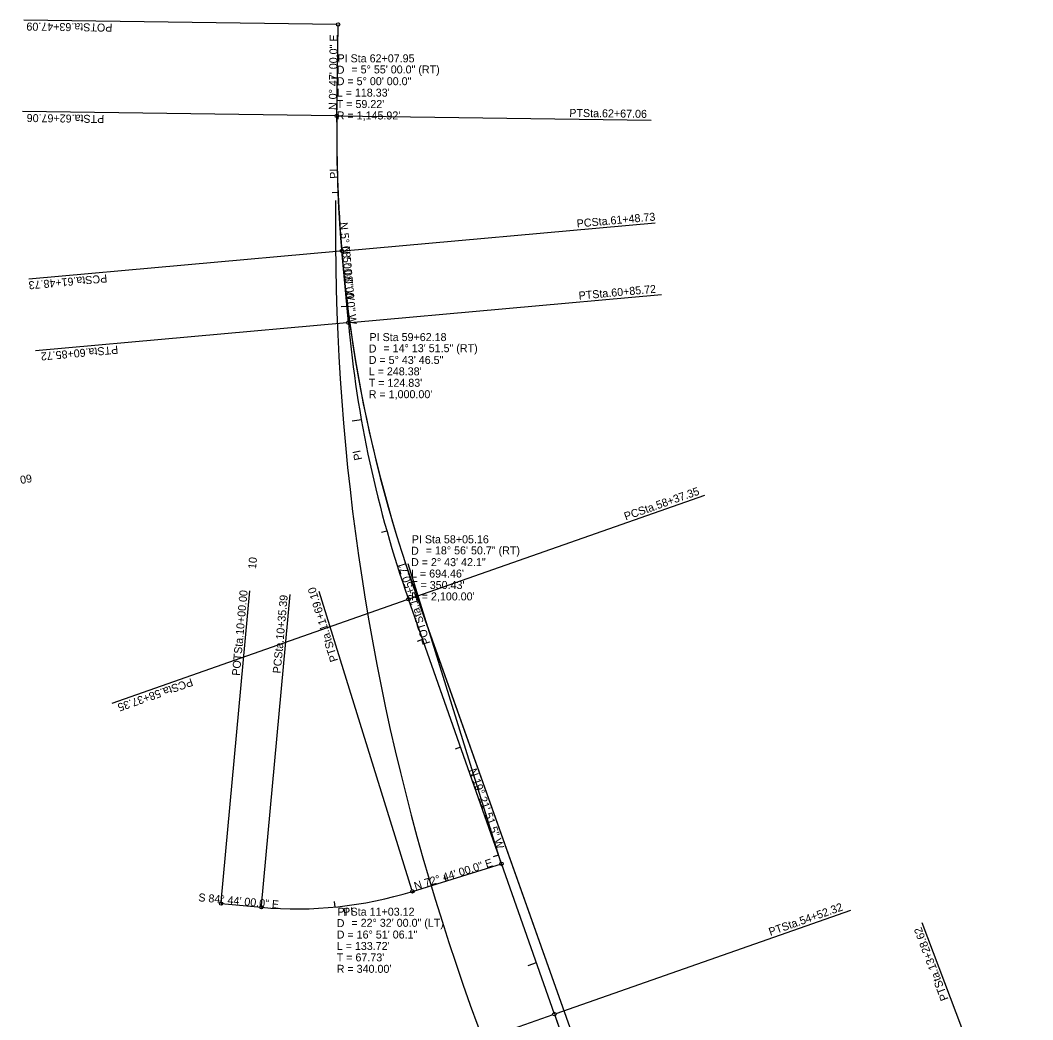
# Model space of a CAD drawing. Extents: x 1615740 to 1617154, y 899624 to 904812.
# Drawn here: x 1615740 to 1616626, y 903937 to 904812 of the extents above; entities that cross this region are included whole.
import ezdxf

# ---------------------------------------------------------------- set-up
doc = ezdxf.new("R2010")
doc.units = 0
for name, color, linetype in [('Default', 7, 'Continuous'), ('Exist Plan Preparation Drainage Flow Arrows', 7, 'Continuous'), ('Exist Plan Preparation Drainage Notes Label', 7, 'Continuous'), ('Exist Structure Minor Pipes CMP 15 Inch Text', 7, 'Continuous'), ('Exist Structure Minor Pipes CMP 24 Inch Text', 7, 'Continuous'), ('Exist Structure Minor Pipes RCP 12 Inch Text', 7, 'Continuous'), ('Exist Structure Minor Pipes RCP 24 Inch Text', 7, 'Continuous'), ('Prop Plan Preparation Sag', 7, 'Continuous'), ('Scratch_Level_7', 7, 'Continuous')]:
    doc.layers.add(name, color=color, linetype=linetype)

msp = doc.modelspace()

# ---------------------------------------------------------------- linework, layer by layer
at = {"layer": 'Default'}
for p, q in [((1616561.34, 902975.04), (1616086.7, 904309.23)), ((1616561.34, 902975.04), (1616086.7, 904309.23)), ((1616342.41, 903590.45), (1616086.73, 904309.16)), ((1616207.75, 903941.79), (1616102.54, 904241.15))]:
    msp.add_line(p, q, dxfattribs=at)
for centre, radius, start, end in [((1617217.29, 904711.44), 1200, 179.21667, 199.58304), ((1617217.29, 904711.44), 1200, 179.21667, 199.58304), ((1618016.2, 904626.61), 2000, 179.21665, 214.80209), ((1618849.35, 904870.2), 2800, 199.3643, 204.77008)]:
    msp.add_arc(centre, radius, start, end, dxfattribs=at)
at = {"layer": 'Exist Plan Preparation Drainage Flow Arrows'}
for p, q in [((1616038.85, 904462.19), (1616030.97, 904460.79)), ((1616038.85, 904462.19), (1616030.97, 904460.79)), ((1616038.85, 904462.19), (1616030.97, 904460.79)), ((1616038.85, 904462.19), (1616030.97, 904460.79)), ((1615916.17, 904038.64), (1615916.9, 904046.61)), ((1615916.17, 904038.64), (1615916.9, 904046.61)), ((1615916.17, 904038.64), (1615916.9, 904046.61)), ((1615916.17, 904038.64), (1615916.9, 904046.61)), ((1616191.94, 903986.77), (1616184.4, 903984.12)), ((1616191.94, 903986.77), (1616184.4, 903984.12)), ((1616191.94, 903986.77), (1616184.4, 903984.12)), ((1616191.94, 903986.77), (1616184.4, 903984.12))]:
    msp.add_line(p, q, dxfattribs=at)
at = {"layer": 'Exist Plan Preparation Drainage Notes Label'}
for p, q in [((1616017.85, 904761.02), (1616012.85, 904761.08)), ((1616017.85, 904761.02), (1616012.85, 904761.08)), ((1616017.85, 904761.02), (1616012.85, 904761.08)), ((1616017.85, 904761.02), (1616012.85, 904761.08)), ((1616018.45, 904661.04), (1616013.45, 904660.81)), ((1616018.45, 904661.04), (1616013.45, 904660.81)), ((1616018.45, 904661.04), (1616013.45, 904660.81)), ((1616018.45, 904661.04), (1616013.45, 904660.81)), ((1616026.25, 904561.35), (1616021.27, 904560.9)), ((1616026.25, 904561.35), (1616021.27, 904560.9)), ((1616026.25, 904561.35), (1616021.27, 904560.9)), ((1616026.25, 904561.35), (1616021.27, 904560.9)), ((1616061.18, 904364.75), (1616056.37, 904363.39)), ((1616061.18, 904364.75), (1616056.37, 904363.39)), ((1616061.18, 904364.75), (1616056.37, 904363.39)), ((1616061.18, 904364.75), (1616056.37, 904363.39)), ((1616092.47, 904269.8), (1616087.75, 904268.14)), ((1616092.47, 904269.8), (1616087.75, 904268.14)), ((1616092.47, 904269.8), (1616087.75, 904268.14)), ((1616092.47, 904269.8), (1616087.75, 904268.14)), ((1616125.63, 904175.46), (1616120.91, 904173.8)), ((1616125.63, 904175.46), (1616120.91, 904173.8)), ((1616125.63, 904175.46), (1616120.91, 904173.8)), ((1616125.63, 904175.46), (1616120.91, 904173.8)), ((1616158.79, 904081.11), (1616154.07, 904079.46)), ((1616158.79, 904081.11), (1616154.07, 904079.46)), ((1616158.79, 904081.11), (1616154.07, 904079.46)), ((1616158.79, 904081.11), (1616154.07, 904079.46)), ((1616113.04, 904058.45), (1616111.55, 904063.23)), ((1616113.04, 904058.45), (1616111.55, 904063.23)), ((1616113.04, 904058.45), (1616111.55, 904063.23)), ((1616113.04, 904058.45), (1616111.55, 904063.23)), ((1616015.92, 904035.59), (1616015.43, 904040.57)), ((1616015.92, 904035.59), (1616015.43, 904040.57)), ((1616015.92, 904035.59), (1616015.43, 904040.57)), ((1616015.92, 904035.59), (1616015.43, 904040.57))]:
    msp.add_line(p, q, dxfattribs=at)
at = {"layer": 'Exist Structure Minor Pipes CMP 24 Inch Text'}
for p, q in [((1616017.33, 904722.71), (1616018.5, 904808.1)), ((1616017.4, 904728.08), (1616018.5, 904808.1)), ((1616027.53, 904547.13), (1616021.89, 904609.89)), ((1616207.75, 903941.79), (1616080.09, 904305.03)), ((1616083.53, 904049.28), (1616161.46, 904073.5)), ((1615916.17, 904038.64), (1615951.41, 904035.39))]:
    msp.add_line(p, q, dxfattribs=at)
for centre, radius, start, end in [((1617163.21, 904712.42), 1145.92, 179.21667, 185.13333), ((1617023.52, 904636.61), 1000, 185.13333, 199.3643), ((1615982.61, 904373.96), 340, 264.73333, 287.26667), ((1618849.35, 904870.2), 2800, 199.3643, 205.88101)]:
    msp.add_arc(centre, radius, start, end, dxfattribs=at)
at = {"layer": 'Exist Structure Minor Pipes RCP 12 Inch Text'}
msp.add_line((1616561.34, 902975.02), (1616086.69, 904309.48), dxfattribs=at)
msp.add_arc((1617217.31, 904711.62), 1200, 179.31667, 199.57988, dxfattribs=at)
at = {"layer": 'Prop Plan Preparation Sag'}
for p, q in [((1616017, 904808.12), (1615743.52, 904811.86)), ((1616017, 904808.12), (1615743.52, 904811.86)), ((1616017, 904808.12), (1615743.52, 904811.86)), ((1616017, 904808.12), (1615743.52, 904811.86)), ((1616015.9, 904728.1), (1615742.43, 904731.84)), ((1616018.9, 904728.06), (1616292.38, 904724.32)), ((1616018.9, 904728.06), (1616292.38, 904724.32)), ((1616018.9, 904728.06), (1616292.38, 904724.32)), ((1616023.39, 904610.02), (1616295.79, 904634.49)), ((1616023.39, 904610.02), (1616295.79, 904634.49)), ((1616023.39, 904610.02), (1616295.79, 904634.49)), ((1616020.4, 904609.75), (1615748, 904585.28)), ((1616029.02, 904547.27), (1616301.43, 904571.74)), ((1616029.02, 904547.27), (1616301.43, 904571.74)), ((1616029.02, 904547.27), (1616301.43, 904571.74)), ((1616026.04, 904547), (1615753.63, 904522.53)), ((1616081.5, 904305.53), (1616339.53, 904396.21)), ((1616081.5, 904305.53), (1616339.53, 904396.21)), ((1616081.5, 904305.53), (1616339.53, 904396.21)), ((1616161.02, 904074.93), (1616079.84, 904336.11)), ((1616161.02, 904074.93), (1616079.84, 904336.11)), ((1616161.02, 904074.93), (1616079.84, 904336.11)), ((1616161.02, 904074.93), (1616079.84, 904336.11)), ((1616078.67, 904304.53), (1615820.65, 904213.85)), ((1615916.3, 904040.13), (1615941.41, 904312.48)), ((1615916.3, 904040.13), (1615941.41, 904312.48)), ((1615916.3, 904040.13), (1615941.41, 904312.48)), ((1615916.3, 904040.13), (1615941.41, 904312.48)), ((1615951.54, 904036.89), (1615976.65, 904309.23)), ((1615951.54, 904036.89), (1615976.65, 904309.23)), ((1615951.54, 904036.89), (1615976.65, 904309.23)), ((1615951.54, 904036.89), (1615976.65, 904309.23)), ((1616083.09, 904050.71), (1616001.91, 904311.89)), ((1616083.09, 904050.71), (1616001.91, 904311.89)), ((1616083.09, 904050.71), (1616001.91, 904311.89)), ((1616083.09, 904050.71), (1616001.91, 904311.89)), ((1616209.17, 903942.29), (1616467.2, 904032.97)), ((1616209.17, 903942.29), (1616467.2, 904032.97)), ((1616209.17, 903942.29), (1616467.2, 904032.97)), ((1616626.29, 903765.86), (1616529.62, 904021.7)), ((1616206.34, 903941.29), (1615948.31, 903850.61))]:
    msp.add_line(p, q, dxfattribs=at)
for centre in [(1616018.5, 904808.1), (1616018.5, 904808.1), (1616018.5, 904808.1), (1616018.5, 904808.1), (1616017.4, 904728.08), (1616017.4, 904728.08), (1616017.4, 904728.08), (1616017.4, 904728.08), (1616021.89, 904609.89), (1616021.89, 904609.89), (1616021.89, 904609.89), (1616021.89, 904609.89), (1616027.53, 904547.13), (1616027.53, 904547.13), (1616027.53, 904547.13), (1616027.53, 904547.13), (1616080.09, 904305.03), (1616080.09, 904305.03), (1616080.09, 904305.03), (1616080.09, 904305.03), (1616161.46, 904073.5), (1616161.46, 904073.5), (1616161.46, 904073.5), (1616161.46, 904073.5), (1616083.53, 904049.28), (1616083.53, 904049.28), (1616083.53, 904049.28), (1616083.53, 904049.28), (1615916.17, 904038.64), (1615916.17, 904038.64), (1615916.17, 904038.64), (1615916.17, 904038.64), (1615951.41, 904035.39), (1615951.41, 904035.39), (1615951.41, 904035.39), (1615951.41, 904035.39), (1616207.75, 903941.79), (1616207.75, 903941.79), (1616207.75, 903941.79), (1616207.75, 903941.79)]:
    msp.add_circle(centre, 1.5, dxfattribs=at)

# ---------------------------------------------------------------- texts
at = {"layer": 'Default'}
for rotation, p in [(92.175, (1616018.43, 904673.26)), (92.175, (1616018.43, 904673.26)), (102.24882, (1616039.74, 904427.45)), (102.24882, (1616039.74, 904427.45)), (6, (1616023.36, 904027.64)), (6, (1616023.36, 904027.64))]:
    msp.add_text('PI ', height=7, rotation=rotation, dxfattribs=at).set_placement(p)
at = {"layer": 'Exist Structure Minor Pipes CMP 15 Inch Text'}
for s, rotation, p in [('N 0%%d 47\' 00.0" E', 89.21667, (1616017.27, 904733.22)), ('N 0%%d 47\' 00.0" E', 89.21667, (1616017.27, 904733.22)), ('N 0%%d 47\' 00.0" E', 89.21667, (1616017.27, 904733.22)), ('N 0%%d 47\' 00.0" E', 89.21667, (1616017.27, 904733.22)), ('N 5%%d 08\' 00.0" W', 275.13333, (1616019.86, 904634.73)), ('N 5%%d 08\' 00.0" W', 275.13333, (1616019.86, 904634.73)), ('N 5%%d 08\' 00.0" W', 275.13333, (1616021.74, 904613.76)), ('N 5%%d 08\' 00.0" W', 275.13333, (1616021.74, 904613.76)), ('N 5%%d 08\' 00.0" W', 275.13333, (1616021.74, 904613.76)), ('N 5%%d 08\' 00.0" W', 275.13333, (1616021.74, 904613.76)), ('N 19%%d 21\' 51.5" W', 289.3643, (1616132.87, 904155.45)), ('N 19%%d 21\' 51.5" W', 289.3643, (1616132.87, 904155.45)), ('N 19%%d 21\' 51.5" W', 289.3643, (1616132.87, 904155.45)), ('N 19%%d 21\' 51.5" W', 289.3643, (1616132.87, 904155.45)), ('N 72%%d 44\' 00.0" E', 17.26667, (1616086.23, 904050.33)), ('N 72%%d 44\' 00.0" E', 17.26667, (1616086.23, 904050.33)), ('S 84%%d 44\' 00.0" E', 354.73333, (1615896, 904040.7)), ('S 84%%d 44\' 00.0" E', 354.73333, (1615896, 904040.7))]:
    msp.add_text(s, height=7, rotation=rotation, dxfattribs=at).set_placement(p)
at = {"layer": 'Exist Structure Minor Pipes RCP 24 Inch Text'}
for s, p in [('PI Sta 62+07.95', (1616018, 904775)), ('PI Sta 62+07.95', (1616018, 904775)), ('PI Sta 62+07.95', (1616018, 904775)), ('PI Sta 62+07.95', (1616018, 904775)), ('D', (1616017.33, 904765)), ('D', (1616017.33, 904765)), ('D', (1616017.33, 904765)), ('D', (1616017.33, 904765)), ('= 5%%d 55\' 00.0" (RT)', (1616030.18, 904765.3)), ('= 5%%d 55\' 00.0" (RT)', (1616030.18, 904765.3)), ('= 5%%d 55\' 00.0" (RT)', (1616030.18, 904765.3)), ('= 5%%d 55\' 00.0" (RT)', (1616030.18, 904765.3)), ('D = 5%%d 00\' 00.0"', (1616017.33, 904755)), ('D = 5%%d 00\' 00.0"', (1616017.33, 904755)), ('D = 5%%d 00\' 00.0"', (1616017.33, 904755)), ('D = 5%%d 00\' 00.0"', (1616017.33, 904755)), ("L = 118.33'", (1616017.33, 904745)), ("L = 118.33'", (1616017.33, 904745)), ("L = 118.33'", (1616017.33, 904745)), ("L = 118.33'", (1616017.33, 904745)), ("T = 59.22'", (1616017.33, 904735)), ("T = 59.22'", (1616017.33, 904735)), ("T = 59.22'", (1616017.33, 904735)), ("T = 59.22'", (1616017.33, 904735)), ("R = 1,145.92'", (1616017.33, 904725)), ("R = 1,145.92'", (1616017.33, 904725)), ("R = 1,145.92'", (1616017.33, 904725)), ("R = 1,145.92'", (1616017.33, 904725)), ('PI Sta 59+62.18', (1616046, 904531)), ('PI Sta 59+62.18', (1616046, 904531)), ('PI Sta 59+62.18', (1616046, 904531)), ('PI Sta 59+62.18', (1616046, 904531)), ('D', (1616045.33, 904521)), ('D', (1616045.33, 904521)), ('D', (1616045.33, 904521)), ('D', (1616045.33, 904521)), ('= 14%%d 13\' 51.5" (RT)', (1616058.18, 904521.3)), ('= 14%%d 13\' 51.5" (RT)', (1616058.18, 904521.3)), ('= 14%%d 13\' 51.5" (RT)', (1616058.18, 904521.3)), ('= 14%%d 13\' 51.5" (RT)', (1616058.18, 904521.3)), ('D = 5%%d 43\' 46.5"', (1616045.33, 904511)), ('D = 5%%d 43\' 46.5"', (1616045.33, 904511)), ('D = 5%%d 43\' 46.5"', (1616045.33, 904511)), ('D = 5%%d 43\' 46.5"', (1616045.33, 904511)), ("L = 248.38'", (1616045.33, 904501)), ("L = 248.38'", (1616045.33, 904501)), ("L = 248.38'", (1616045.33, 904501)), ("L = 248.38'", (1616045.33, 904501)), ("T = 124.83'", (1616045.33, 904491)), ("T = 124.83'", (1616045.33, 904491)), ("T = 124.83'", (1616045.33, 904491)), ("T = 124.83'", (1616045.33, 904491)), ("R = 1,000.00'", (1616045.33, 904481)), ("R = 1,000.00'", (1616045.33, 904481)), ("R = 1,000.00'", (1616045.33, 904481)), ("R = 1,000.00'", (1616045.33, 904481)), ('PI Sta 58+05.16', (1616083, 904354)), ('PI Sta 58+05.16', (1616083, 904354)), ('D', (1616082.33, 904344)), ('D', (1616082.33, 904344)), ('= 18%%d 56\' 50.7" (RT)', (1616095.18, 904344.3)), ('= 18%%d 56\' 50.7" (RT)', (1616095.18, 904344.3)), ('D = 2%%d 43\' 42.1"', (1616082.33, 904334)), ('D = 2%%d 43\' 42.1"', (1616082.33, 904334)), ("L = 694.46'", (1616082.33, 904324)), ("L = 694.46'", (1616082.33, 904324)), ("T = 350.43'", (1616082.33, 904314)), ("T = 350.43'", (1616082.33, 904314)), ("R = 2,100.00'", (1616082.33, 904304)), ("R = 2,100.00'", (1616082.33, 904304)), ('PI Sta 11+03.12', (1616018, 904028)), ('PI Sta 11+03.12', (1616018, 904028)), ('D', (1616017.33, 904018)), ('D', (1616017.33, 904018)), ('= 22%%d 32\' 00.0" (LT)', (1616030.18, 904018.3)), ('= 22%%d 32\' 00.0" (LT)', (1616030.18, 904018.3)), ('D = 16%%d 51\' 06.1"', (1616017.33, 904008)), ('D = 16%%d 51\' 06.1"', (1616017.33, 904008)), ("L = 133.72'", (1616017.33, 903998)), ("L = 133.72'", (1616017.33, 903998)), ("T = 67.73'", (1616017.33, 903988)), ("T = 67.73'", (1616017.33, 903988)), ("R = 340.00'", (1616017.33, 903978)), ("R = 340.00'", (1616017.33, 903978))]:
    msp.add_text(s, height=7, dxfattribs=at).set_placement(p)
at = {"layer": 'Prop Plan Preparation Sag'}
for s, rotation, p in [('POTSta.63+47.09', 179.21667, (1615821.08, 904808.8)), ('POTSta.63+47.09', 179.21667, (1615821.08, 904808.8)), ('POTSta.63+47.09', 179.21667, (1615821.08, 904808.8)), ('POTSta.63+47.09', 179.21667, (1615821.08, 904808.8)), ('PTSta.62+67.06', 179.21667, (1615814.04, 904728.86)), ('PTSta.62+67.06', 359.21667, (1616220.77, 904727.3)), ('PTSta.62+67.06', 359.21667, (1616220.77, 904727.3)), ('PTSta.62+67.06', 359.21667, (1616220.77, 904727.3)), ('PCSta.61+48.73', 5.13333, (1616227.6, 904630.37)), ('PCSta.61+48.73', 5.13333, (1616227.6, 904630.37)), ('PCSta.61+48.73', 5.13333, (1616227.6, 904630.37)), ('PCSta.61+48.73', 185.13333, (1615816.18, 904589.4)), ('PTSta.60+85.72', 5.13333, (1616229.29, 904567.26)), ('PTSta.60+85.72', 5.13333, (1616229.29, 904567.26)), ('PTSta.60+85.72', 5.13333, (1616229.29, 904567.26)), ('PTSta.60+85.72', 185.13333, (1615825.77, 904527)), ('PCSta.58+37.35', 19.3643, (1616270.19, 904373.96)), ('PCSta.58+37.35', 19.3643, (1616270.19, 904373.96)), ('PCSta.58+37.35', 19.3643, (1616270.19, 904373.96)), ('POTSta.12+50.71', 107.26667, (1616099.36, 904266.57)), ('POTSta.12+50.71', 107.26667, (1616099.36, 904266.57)), ('POTSta.12+50.71', 107.26667, (1616099.36, 904266.57)), ('POTSta.12+50.71', 107.26667, (1616099.36, 904266.57)), ('PTSta.11+69.10', 107.26667, (1616018.61, 904251.41)), ('PTSta.11+69.10', 107.26667, (1616018.61, 904251.41)), ('PTSta.11+69.10', 107.26667, (1616018.61, 904251.41)), ('PTSta.11+69.10', 107.26667, (1616018.61, 904251.41)), ('POTSta.10+00.00', 84.73333, (1615932.52, 904237.81)), ('POTSta.10+00.00', 84.73333, (1615932.52, 904237.81)), ('POTSta.10+00.00', 84.73333, (1615932.52, 904237.81)), ('POTSta.10+00.00', 84.73333, (1615932.52, 904237.81)), ('PCSta.10+35.39', 84.73333, (1615968.24, 904239.83)), ('PCSta.10+35.39', 84.73333, (1615968.24, 904239.83)), ('PCSta.10+35.39', 84.73333, (1615968.24, 904239.83)), ('PCSta.10+35.39', 84.73333, (1615968.24, 904239.83)), ('PCSta.58+37.35', 199.3643, (1615889.99, 904236.1)), ('PTSta.54+52.32', 19.3643, (1616396.71, 904010.32)), ('PTSta.54+52.32', 19.3643, (1616396.71, 904010.32)), ('PTSta.54+52.32', 19.3643, (1616396.71, 904010.32)), ('PTSta.13+28.62', 110.69761, (1616552.66, 903955.06))]:
    msp.add_text(s, height=7, rotation=rotation, dxfattribs=at).set_placement(p)
at = {"layer": 'Scratch_Level_7'}
for s, rotation, p in [('60', 190.0449, (1615750.01, 904414.58)), ('60', 190.0449, (1615750.01, 904414.58)), ('60', 190.0449, (1615750.01, 904414.58)), ('60', 190.0449, (1615750.01, 904414.58)), ('10', 84.73333, (1615946.65, 904331.22)), ('10', 84.73333, (1615946.65, 904331.22)), ('10', 84.73333, (1615946.65, 904331.22)), ('10', 84.73333, (1615946.65, 904331.22))]:
    msp.add_text(s, height=7, rotation=rotation, dxfattribs=at).set_placement(p)

doc.saveas('drawing.dxf')
